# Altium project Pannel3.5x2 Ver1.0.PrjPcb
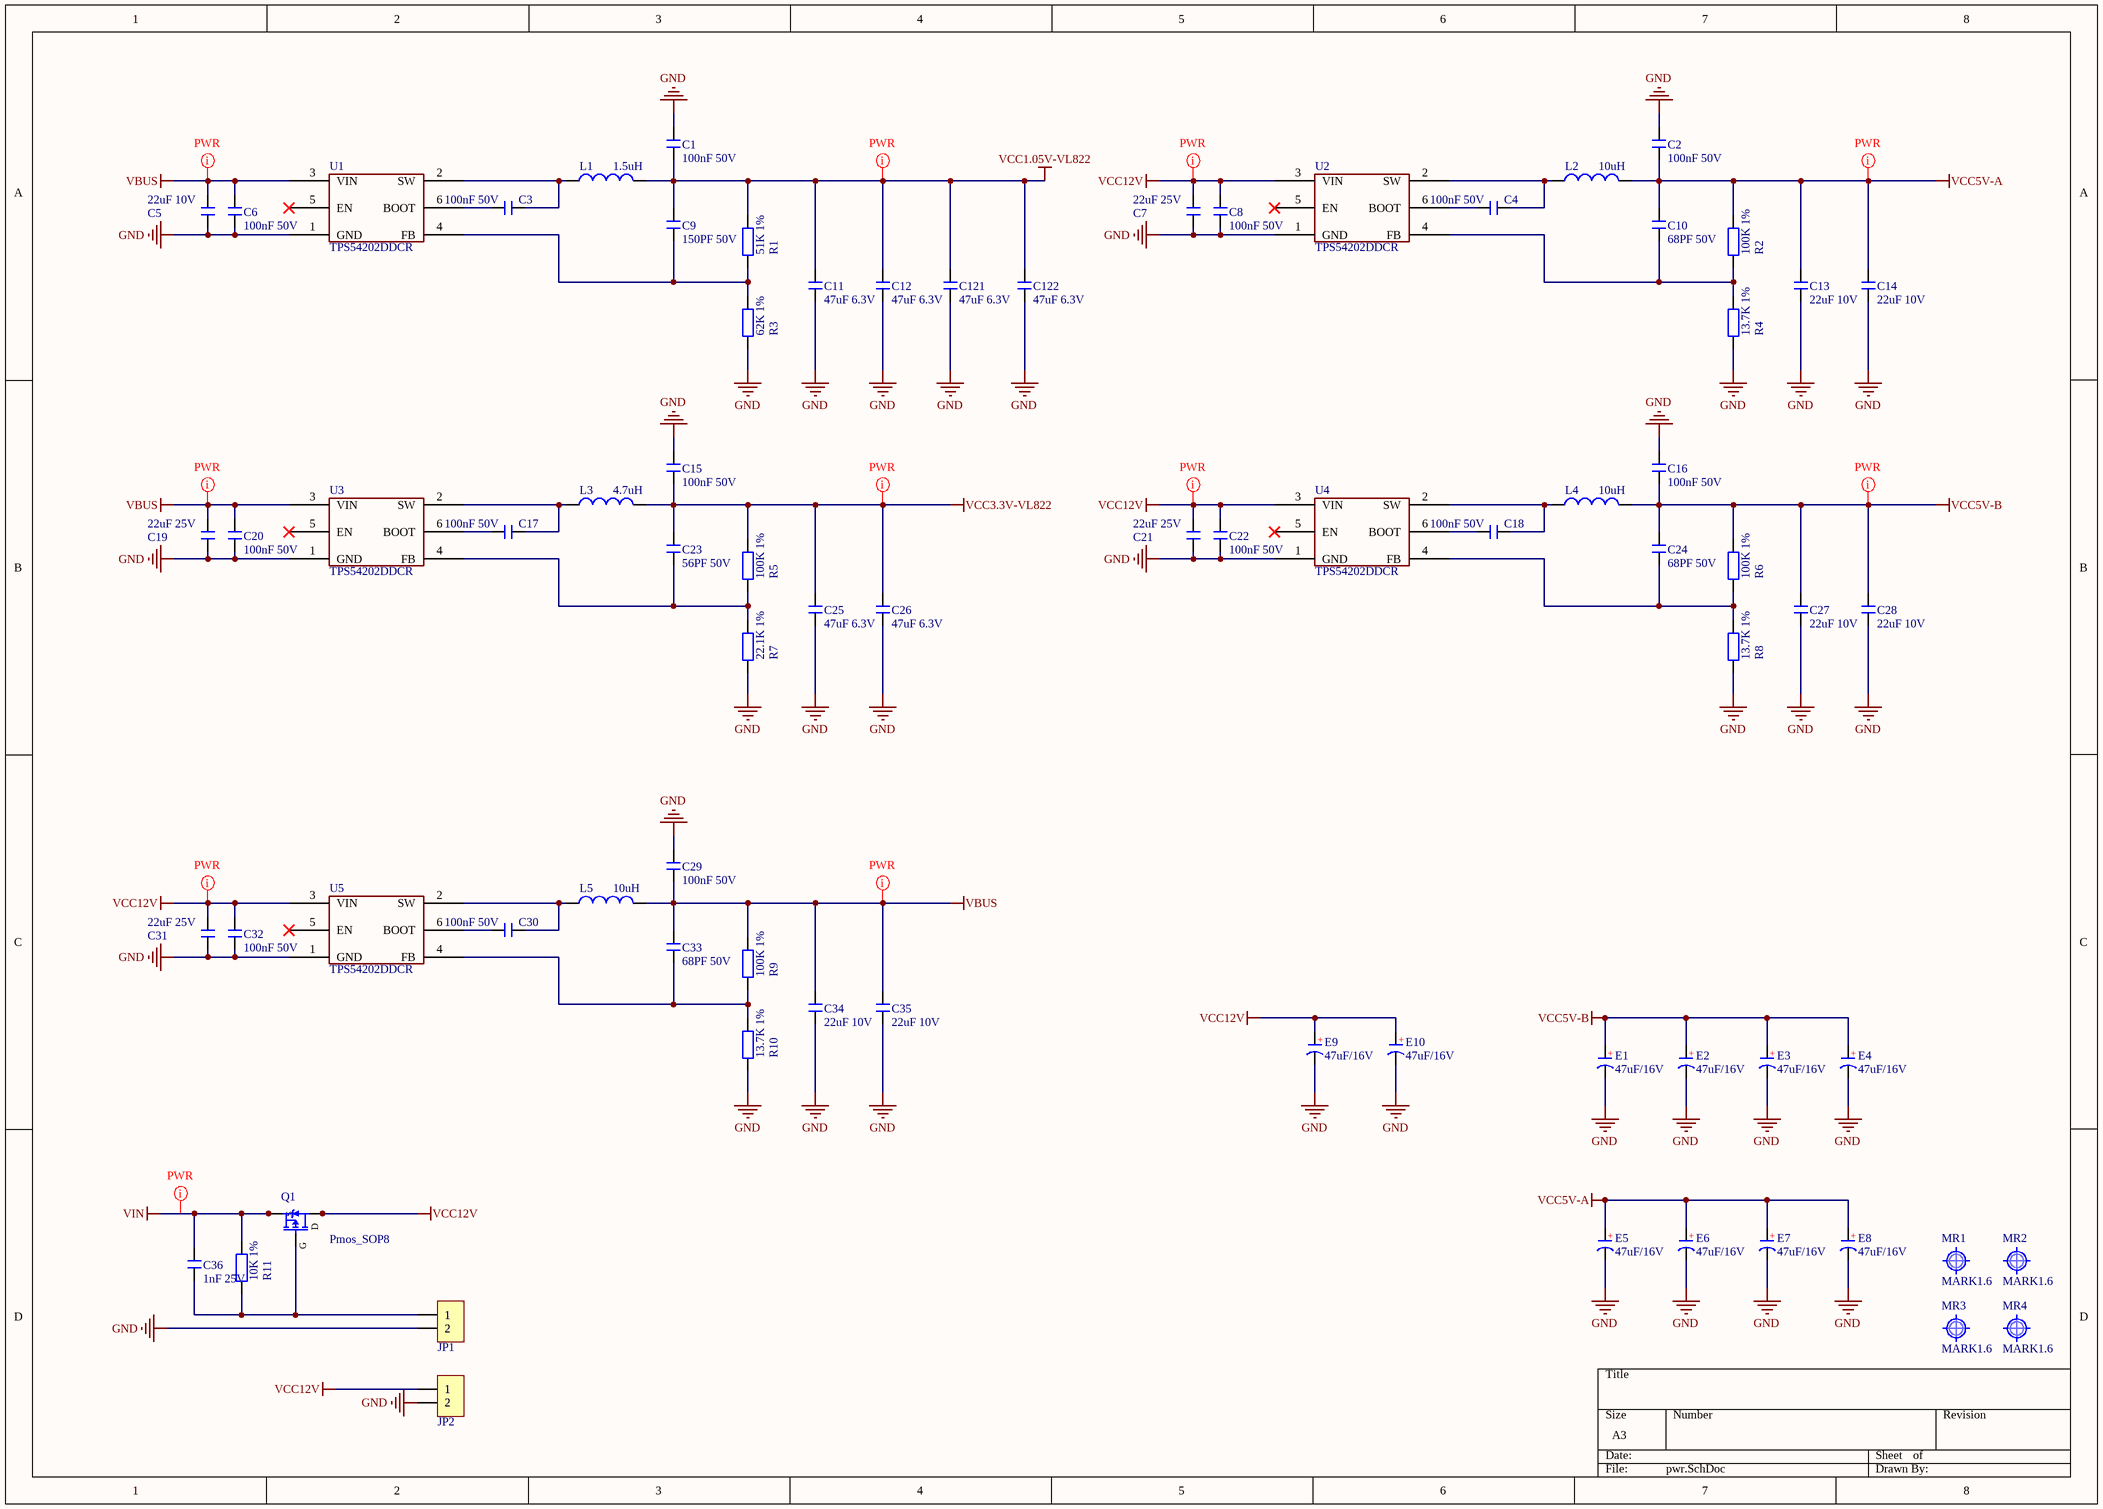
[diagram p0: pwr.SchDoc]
4 sheets, 222 parts. Net scope: global (net labels, ports and power ports of the same name join across sheets).
Board file: Pannel3.5x2 Ver0.2.PcbDoc
Sheets:
  pwr.SchDoc
  connector.SchDoc
  jmb575.SchDoc
  vl822.SchDoc

## Sheet pwr.SchDoc
size A3; SheetNumber: 1; SheetTotal: 4

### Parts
C1  100nF 50V  [C0402_L]
C2  100nF 50V  [C0402_L]
C3  100nF 50V  [C0402_L]
C4  100nF 50V  [C0402_L]
C5  22uF 10V  [C0805_L]
C6  100nF 50V  [C0402_L]
C7  22uF 25V  [C0805_L]
C8  100nF 50V  [C0402_L]
C9  150PF 50V  [C0402_L]
C10  68PF 50V  [C0402_L]
C11  47uF 6.3V  [C0805_L]
C12  47uF 6.3V  [C0805_L]
C13  22uF 10V  [C0805_L]
C14  22uF 10V  [C0805_L]
C15  100nF 50V  [C0402_L]
C16  100nF 50V  [C0402_L]
C17  100nF 50V  [C0402_L]
C18  100nF 50V  [C0402_L]
C19  22uF 25V  [C0805_L]
C20  100nF 50V  [C0402_L]
C21  22uF 25V  [C0805_L]
C22  100nF 50V  [C0402_L]
C23  56PF 50V  [C0402_L]
C24  68PF 50V  [C0402_L]
C25  47uF 6.3V  [C0805_L]
C26  47uF 6.3V  [C0805_L]
C27  22uF 10V  [C0805_L]
C28  22uF 10V  [C0805_L]
C29  100nF 50V  [C0402_L]
C30  100nF 50V  [C0402_L]
C31  22uF 25V  [C0805_L]
C32  100nF 50V  [C0402_L]
C33  68PF 50V  [C0402_L]
C34  22uF 10V  [C0805_L]
C35  22uF 10V  [C0805_L]
C36  1nF 25V  [C0402_L]
C121  47uF 6.3V  [C0805_L]
C122  47uF 6.3V  [C0805_L]
E1  47uF/16V  [CS 6*4 - R]
E2  47uF/16V  [CS 6*4 - R]
E3  47uF/16V  [CS 6*4 - R]
E4  47uF/16V  [CS 6*4 - R]
E5  47uF/16V  [CS 6*4 - R]
E6  47uF/16V  [CS 6*4 - R]
E7  47uF/16V  [CS 6*4 - R]
E8  47uF/16V  [CS 6*4 - R]
E9  47uF/16V  [CS 6*4 - R]
E10  47uF/16V  [CS 6*4 - R]
JP1  HDR-1X2  [ZH1.5-WS-2P]  (value not drawn)
JP2  HDR-1X2  [XH2.54-WS-2P]  (value not drawn)
L1  1.5uH  [SMMS0420]
L2  10uH  [SMMS0420]
L3  4.7uH  [SMMS0420]
L4  10uH  [SMMS0420]
L5  10uH  [SMMS0420]
MR1  MARK1.6  [Mark 1]
MR2  MARK1.6  [Mark 1]
MR3  MARK1.6  [Mark 1]
MR4  MARK1.6  [Mark 1]
Q1  Pmos_SOP8  [SOP8_L]
R1  51K 1%  [R0402_L]
R2  100K 1%  [R0402_L]
R3  62K 1%  [R0402_L]
R4  13.7K 1%  [R0402_L]
R5  100K 1%  [R0402_L]
R6  100K 1%  [R0402_L]
R7  22.1K 1%  [R0402_L]
R8  13.7K 1%  [R0402_L]
R9  100K 1%  [R0402_L]
R10  13.7K 1%  [R0402_L]
R11  10K 1%  [R0402_L]
U1  TPS54202DDCR  [SOT23-6L]
U2  TPS54202DDCR  [SOT23-6L]
U3  TPS54202DDCR  [SOT23-6L]
U4  TPS54202DDCR  [SOT23-6L]
U5  TPS54202DDCR  [SOT23-6L]

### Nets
GND: C1.2 C2.2 C5.1 C6.1 C7.1 C8.1 C11.2 C12.2 C13.2 C14.2 C15.2 C16.2 C19.1 C20.1 C21.1 C22.1 C25.2 C26.2 C27.2 C28.2 C29.2 C31.1 C32.1 C34.2 C35.2 C121.2 C122.2 E1.2(K) E2.2(K) E3.2(K) E4.2(K) E5.2(K) E6.2(K) E7.2(K) E8.2(K) E9.2(K) E10.2(K) JP1.2 JP2.2 R3.2 R4.2 R7.2 R8.2 R10.2 U1.1(GND) U2.1(GND) U3.1(GND) U4.1(GND) U5.1(GND)
VBUS: C5.2 C6.2 C19.2 C20.2 C29.1 C33.2 C34.1 C35.1 L5.2 R9.1 U1.3(VIN) U3.3(VIN)
VCC1.05V-VL822: C1.1 C9.2 C11.1 C12.1 C121.1 C122.1 L1.2 R1.1
VCC3.3V-VL822: C15.1 C23.2 C25.1 C26.1 L3.2 R5.1
VCC5V-A: C2.1 C10.2 C13.1 C14.1 E5.1(A) E6.1(A) E7.1(A) E8.1(A) L2.2 R2.1
VCC5V-B: C16.1 C24.2 C27.1 C28.1 E1.1(A) E2.1(A) E3.1(A) E4.1(A) L4.2 R6.1
VCC12V: C7.2 C8.2 C21.2 C22.2 C31.2 C32.2 E9.1(A) E10.1(A) JP2.1 Q1.5(D) Q1.6(D) Q1.7(D) Q1.8(D) U2.3(VIN) U4.3(VIN) U5.3(VIN)
VIN: C36.1 Q1.1(S) Q1.2(S) Q1.3(S) R11.1
NetC3_1: C3.1 U1.6(BOOT)
NetC3_2: C3.2 L1.1 U1.2(SW)
NetC4_1: C4.1 U2.6(BOOT)
NetC4_2: C4.2 L2.1 U2.2(SW)
NetC9_1: C9.1 R1.2 R3.1 U1.4(FB)
NetC10_1: C10.1 R2.2 R4.1 U2.4(FB)
NetC17_1: C17.1 U3.6(BOOT)
NetC17_2: C17.2 L3.1 U3.2(SW)
NetC18_1: C18.1 U4.6(BOOT)
NetC18_2: C18.2 L4.1 U4.2(SW)
NetC23_1: C23.1 R5.2 R7.1 U3.4(FB)
NetC24_1: C24.1 R6.2 R8.1 U4.4(FB)
NetC30_1: C30.1 U5.6(BOOT)
NetC30_2: C30.2 L5.1 U5.2(SW)
NetC33_1: C33.1 R9.2 R10.1 U5.4(FB)
NetC36_2: C36.2 JP1.1 Q1.4(G) R11.2

Not connected (* = marked no-connect by the designer): U1 5(EN)*; U2 5(EN)*; U3 5(EN)*; U4 5(EN)*; U5 5(EN)*

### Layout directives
net class PWR: VBUS, VCC1.05V-VL822, VCC3.3V-VL822, VCC5V-A, VCC5V-B, VCC12V, VIN

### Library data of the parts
C1-C36 C121 C122 = C: 无极性贴片电容; 版权归属: 源创客; 材质: X7R
E1-E10 = C-CD: 贴片电解电容; BOM名称: 贴片钽电容; 版权归属: 源创客
JP1 JP2 = Header 2: 2P接插件; 版权归属: 源创客
L1-L5 = L: 小功率贴片电感; 版权归属: 源创客
MR1-MR4 = MARK: 光学定位点; 版权归属: 源创客
Q1 = Pmos_SOP8: BOM名称: 场效应管; 版权归属: 源创客; 描述: P沟道 30V/4.2A
R1-R11 = R: 贴片电阻; 版权归属: 源创客
U1-U5 = TPS54202DDCR: DCDC Convert

## Sheet connector.SchDoc
size A4; SheetNumber: 2; SheetTotal: 4
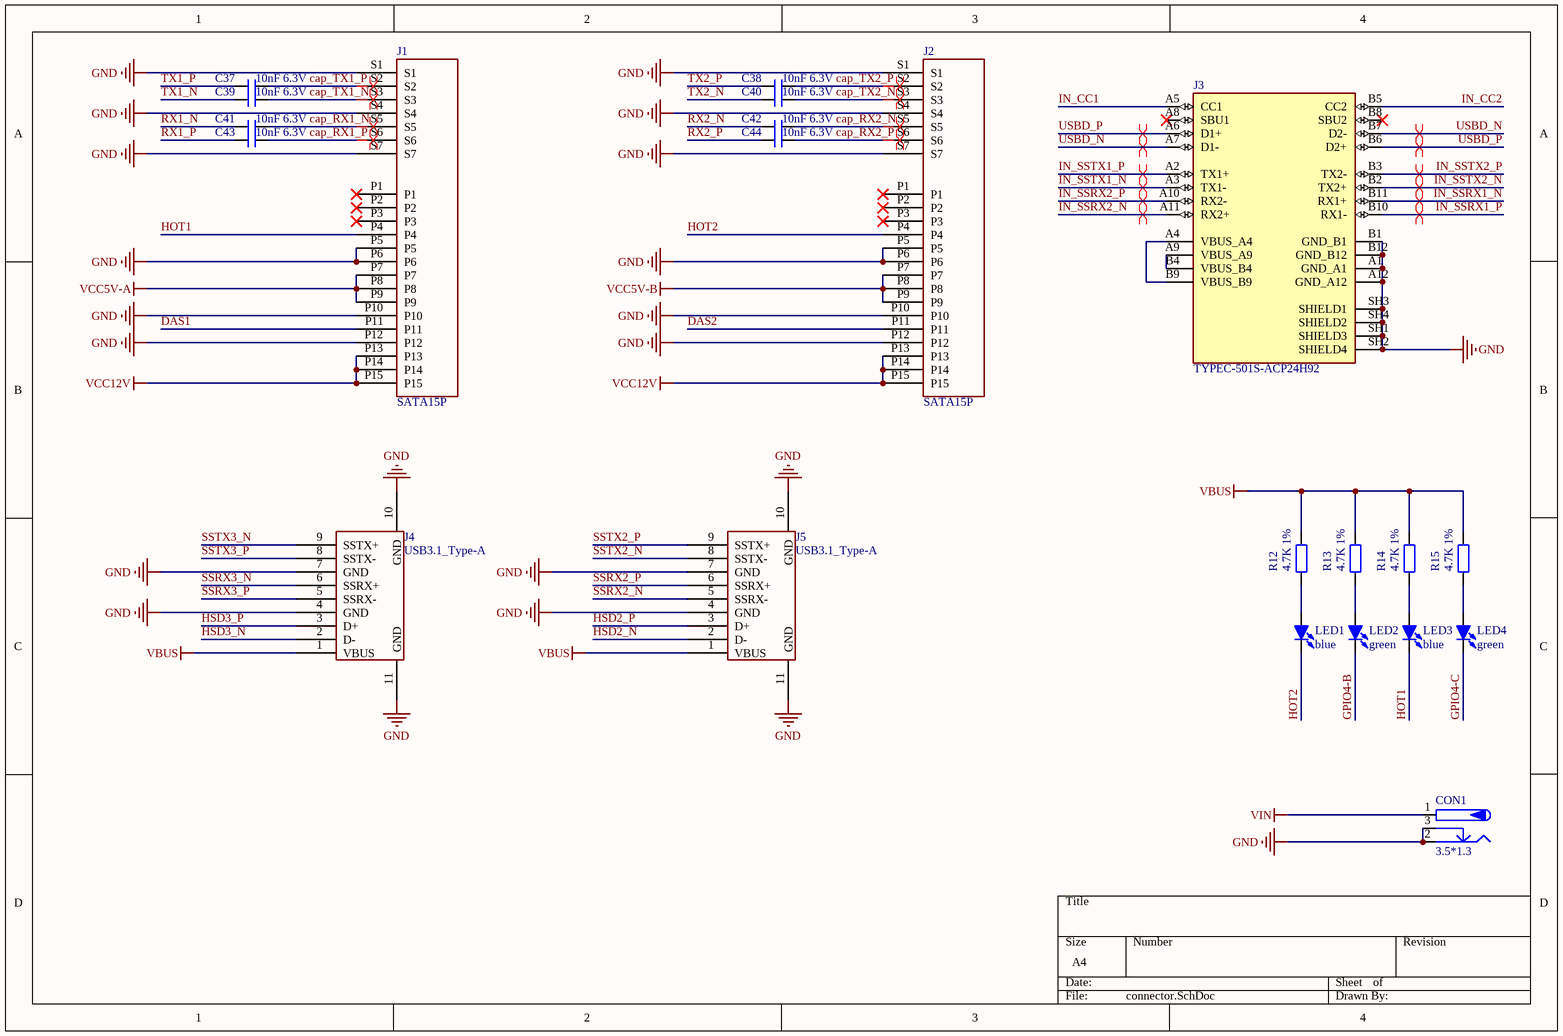
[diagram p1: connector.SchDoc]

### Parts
C37  10nF 6.3V  [C0402_L]
C38  10nF 6.3V  [C0402_L]
C39  10nF 6.3V  [C0402_L]
C40  10nF 6.3V  [C0402_L]
C41  10nF 6.3V  [C0402_L]
C42  10nF 6.3V  [C0402_L]
C43  10nF 6.3V  [C0402_L]
C44  10nF 6.3V  [C0402_L]
CON1  3.5*1.3  [DC-012G-2.5]
J1  SATA15P  [SATA 15P 贴片]
J2  SATA15P  [SATA 15P 贴片]
J3  TYPEC-501S-ACP24H92  [TypeC 24p 直立]
J4  USB3.1_Type-A  [USB3.1_Type-A 立式直插]
J5  USB3.1_Type-A  [USB3.1_Type-A 立式直插]
LED1  blue  [LED 0805B]
LED2  green  [LED 0805G]
LED3  blue  [LED 0805B]
LED4  green  [LED 0805G]
R12  4.7K 1%  [R0402_L]
R13  4.7K 1%  [R0402_L]
R14  4.7K 1%  [R0402_L]
R15  4.7K 1%  [R0402_L]

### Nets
GND: CON1.2 CON1.3 J1.P5 J1.P6 J1.P10 J1.P12 J1.S1 J1.S4 J1.S7 J2.P5 J2.P6 J2.P10 J2.P12 J2.S1 J2.S4 J2.S7 J3.A1(GND_A1) J3.A12(GND_A12) J3.B1(GND_B1) J3.B12(GND_B12) J3.SH1(SHIELD3) J3.SH2(SHIELD4) J3.SH3(SHIELD1) J3.SH4(SHIELD2) J4.4(GND) J4.7(GND) J4.10(GND) J4.11(GND) J5.4(GND) J5.7(GND) J5.10(GND) J5.11(GND)
VBUS: J4.1(VBUS) J5.1(VBUS) R12.1 R13.1 R14.1 R15.1
VCC5V-A: J1.P7 J1.P8 J1.P9
VCC5V-B: J2.P7 J2.P8 J2.P9
VCC12V: J1.P13 J1.P14 J1.P15 J2.P13 J2.P14 J2.P15
VIN: CON1.1
cap_RX1_N: C41.1 J1.S5
cap_RX1_P: C43.1 J1.S6
cap_RX2_N: C42.1 J2.S5
cap_RX2_P: C44.1 J2.S6
cap_TX1_N: C39.1 J1.S3
cap_TX1_P: C37.1 J1.S2
cap_TX2_N: C40.1 J2.S3
cap_TX2_P: C38.1 J2.S2
DAS1: J1.P11
DAS2: J2.P11
GPIO4-B: LED2.2(K)
GPIO4-C: LED4.2(K)
HOT1: J1.P4 LED3.2(K)
HOT2: J2.P4 LED1.2(K)
HSD2_N: J5.2(D-)
HSD2_P: J5.3(D+)
HSD3_N: J4.2(D-)
HSD3_P: J4.3(D+)
IN_CC1: J3.A5(CC1)
IN_CC2: J3.B5(CC2)
IN_SSRX1_N: J3.B11(RX1+)
IN_SSRX1_P: J3.B10(RX1-)
IN_SSRX2_N: J3.A11(RX2+)
IN_SSRX2_P: J3.A10(RX2-)
IN_SSTX1_N: J3.A3(TX1-)
IN_SSTX1_P: J3.A2(TX1+)
IN_SSTX2_N: J3.B2(TX2+)
IN_SSTX2_P: J3.B3(TX2-)
RX1_N: C41.2
RX1_P: C43.2
RX2_N: C42.2
RX2_P: C44.2
SSRX2_N: J5.5(SSRX-)
SSRX2_P: J5.6(SSRX+)
SSRX3_N: J4.6(SSRX+)
SSRX3_P: J4.5(SSRX-)
SSTX2_N: J5.8(SSTX-)
SSTX2_P: J5.9(SSTX+)
SSTX3_N: J4.9(SSTX+)
SSTX3_P: J4.8(SSTX-)
TX1_N: C39.2
TX1_P: C37.2
TX2_N: C40.2
TX2_P: C38.2
USBD_N: J3.A7(D1-) J3.B7(D2-)
USBD_P: J3.A6(D1+) J3.B6(D2+)
NetJ3_A4: J3.A4(VBUS_A4) J3.B9(VBUS_B9)
NetJ3_A9: J3.A9(VBUS_A9) J3.B4(VBUS_B4)
NetLED1_1: LED1.1(A) R12.2
NetLED2_1: LED2.1(A) R13.2
NetLED3_1: LED3.1(A) R14.2
NetLED4_1: LED4.1(A) R15.2

Not connected (* = marked no-connect by the designer): J1 P1* P2* P3*; J2 P1* P2* P3*; J3 A8(SBU1)* B8(SBU2)*

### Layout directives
differential pair: cap_RX1_N, cap_RX1_P, cap_RX2_N, cap_RX2_P, cap_TX1_N, cap_TX1_P, cap_TX2_N, cap_TX2_P, IN_SSRX1_N, IN_SSRX1_P, IN_SSRX2_N, IN_SSRX2_P, IN_SSTX1_N, IN_SSTX1_P, IN_SSTX2_N, IN_SSTX2_P, USBD_N, USBD_P

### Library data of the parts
C37-C44 = C: 无极性贴片电容; 版权归属: 源创客; 材质: X7R
CON1 = P-DC: 低压电源接口; BOM名称: DC电源接口; 版权归属: 源创客
J3 = Typec 24p: USB-C (USB TYPE-C) USB 3.2 Gen 2 (USB 3.1 Gen 2, Superspeed + (USB 3.1)) Receptacle Connector 24 Position Surface Mount, Right Angle; Through Hole; MF: Molex; MP: 1054500101
J4 J5 = USB3.1_Type-A: USB接口
LED1-LED4 = LED-3MM: 插件LED; 版权归属: 源创客
R12-R15 = R: 贴片电阻; 版权归属: 源创客

## Sheet jmb575.SchDoc
size A2; SheetNumber: 3; SheetTotal: 4
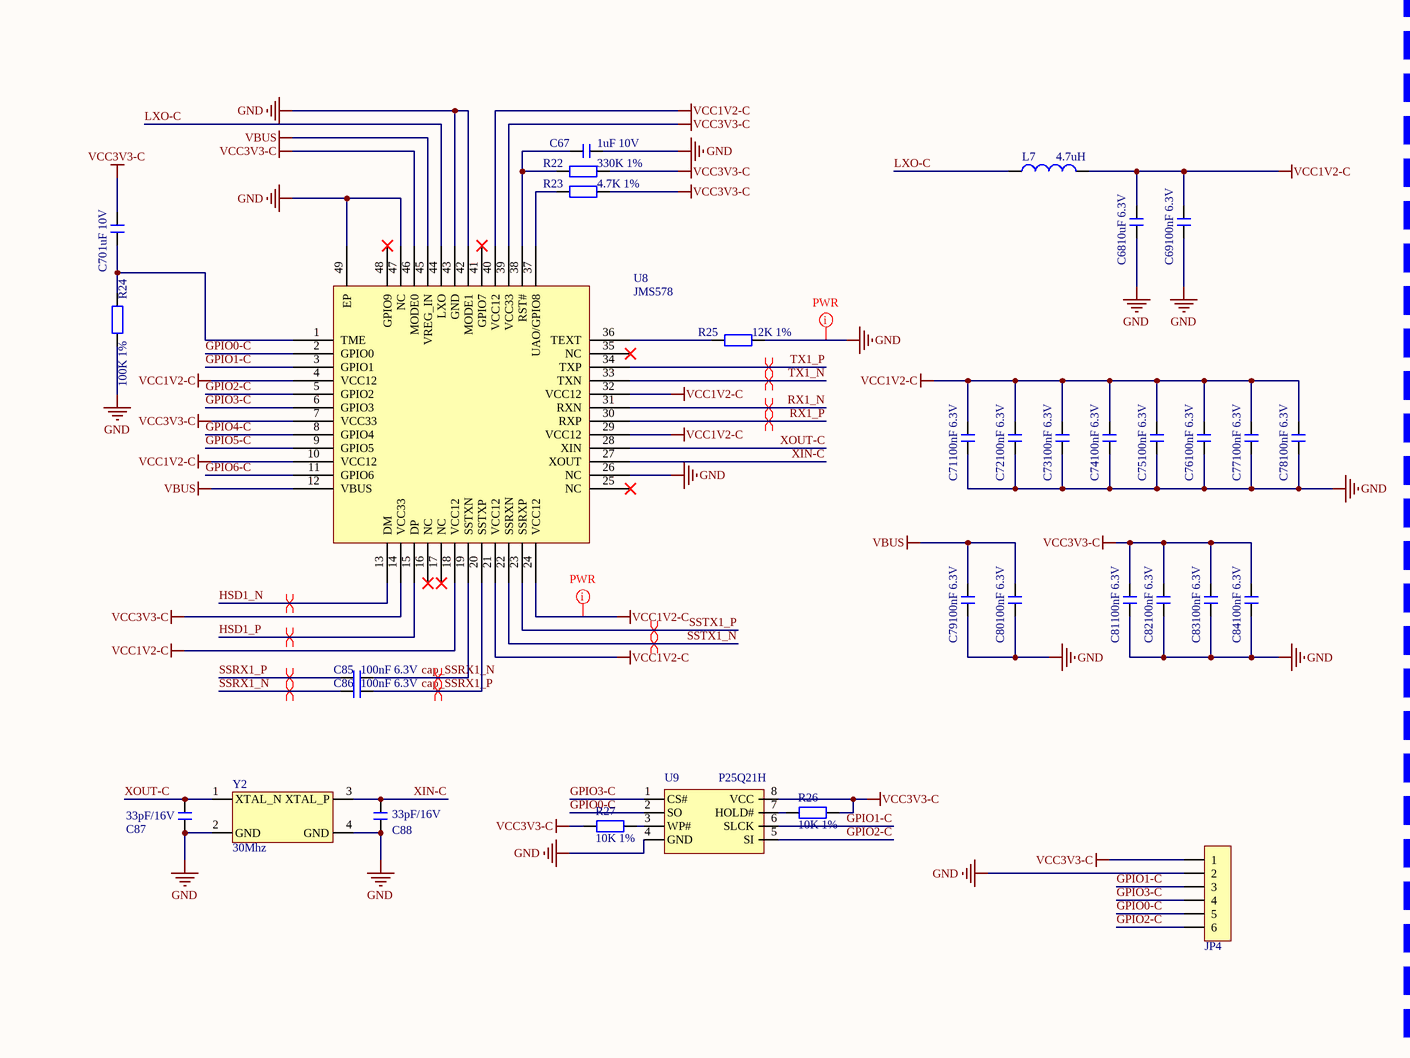
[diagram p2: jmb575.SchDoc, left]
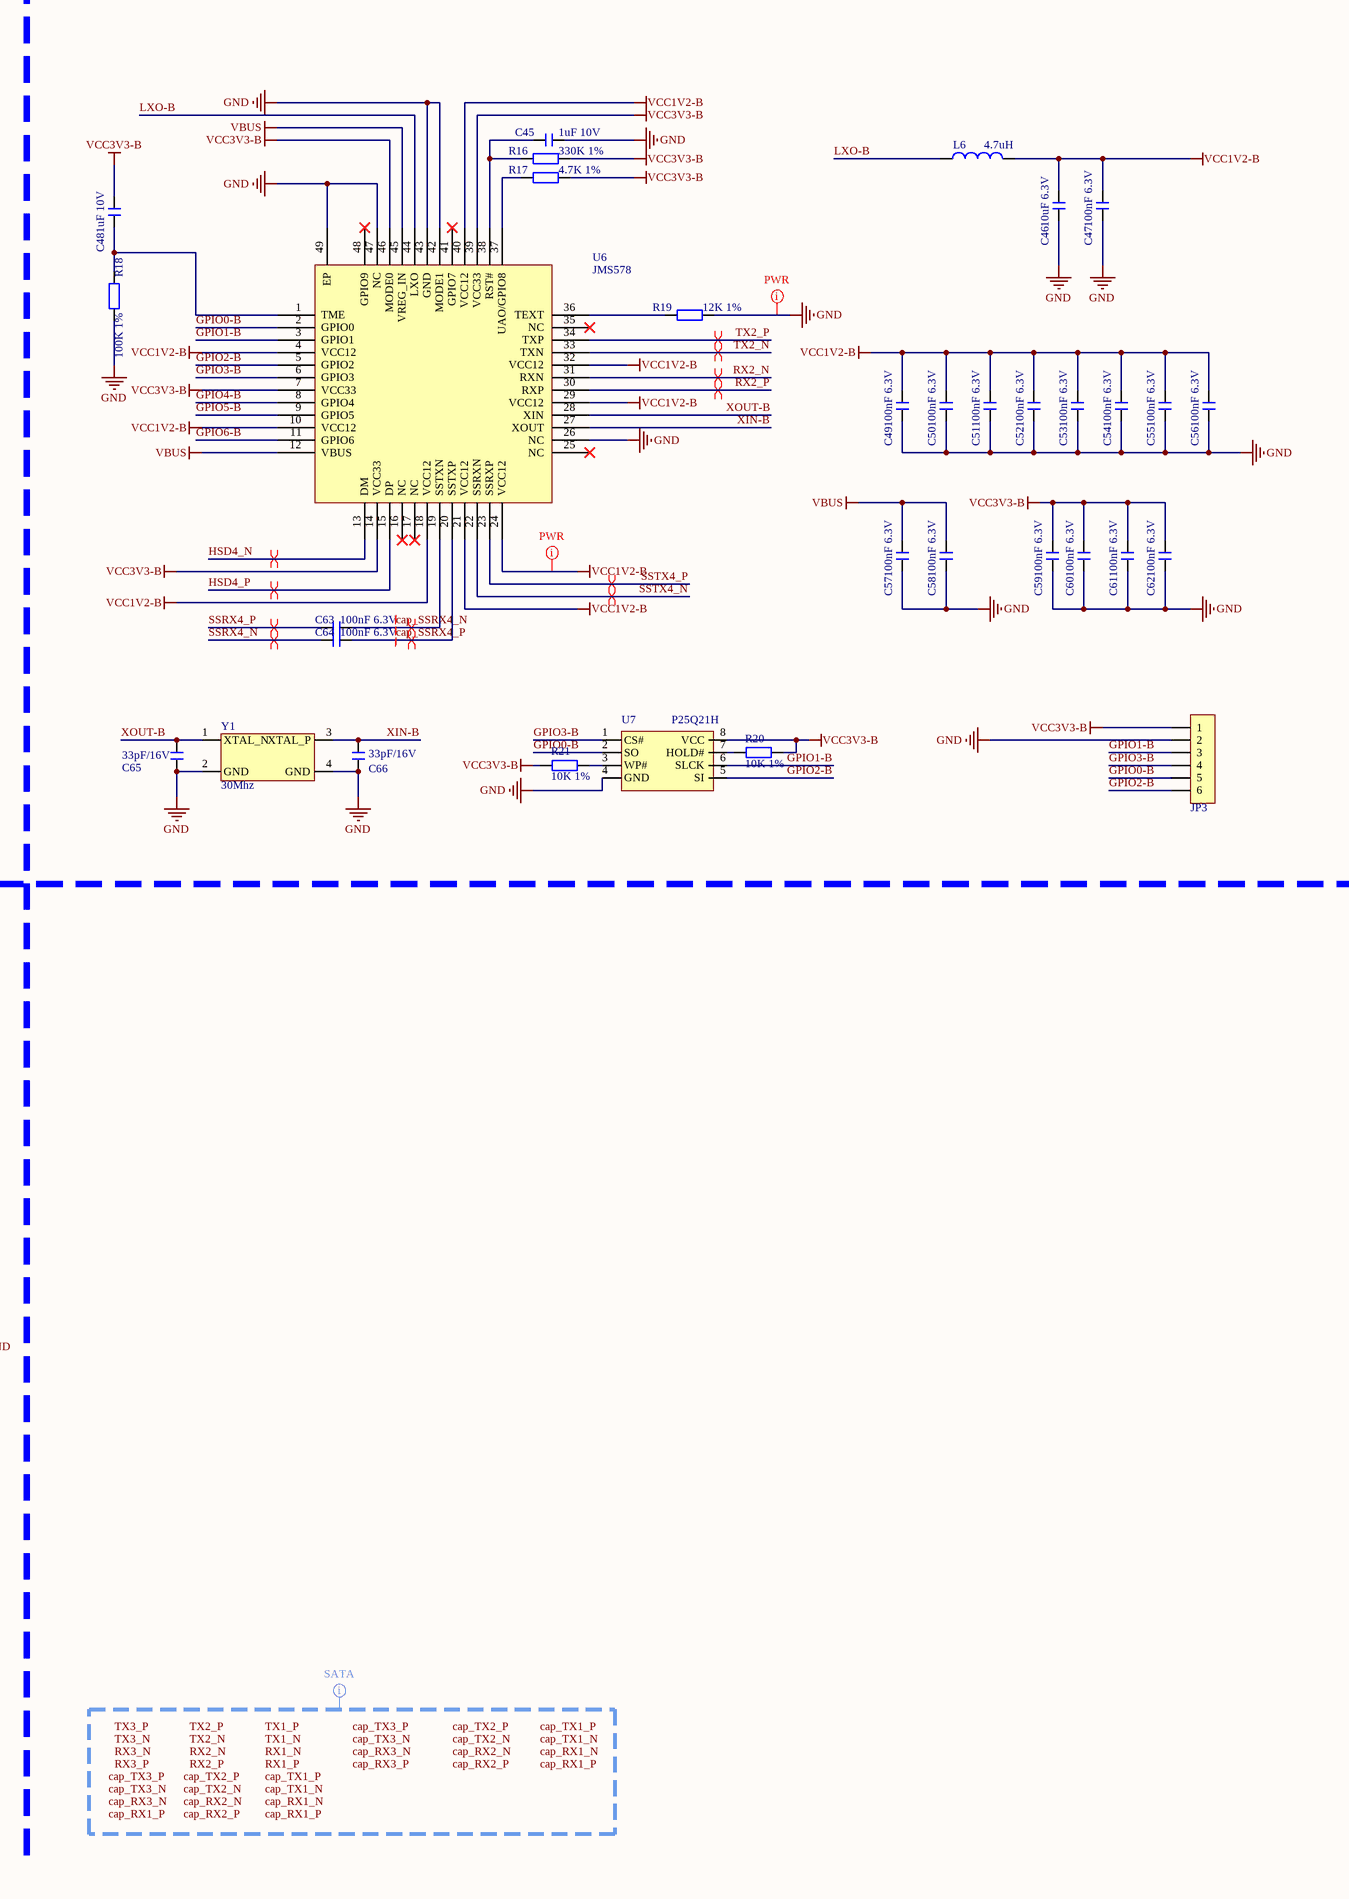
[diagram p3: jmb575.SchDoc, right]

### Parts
C45  1uF 10V  [C0402_L]
C46  10uF 6.3V  [C0603_L]
C47  100nF 6.3V  [C0402_L]
C48  1uF 10V  [C0402_L]
C49  100nF 6.3V  [C0402_L]
C50  100nF 6.3V  [C0402_L]
C51  100nF 6.3V  [C0402_L]
C52  100nF 6.3V  [C0402_L]
C53  100nF 6.3V  [C0402_L]
C54  100nF 6.3V  [C0402_L]
C55  100nF 6.3V  [C0402_L]
C56  100nF 6.3V  [C0402_L]
C57  100nF 6.3V  [C0402_L]
C58  100nF 6.3V  [C0402_L]
C59  100nF 6.3V  [C0402_L]
C60  100nF 6.3V  [C0402_L]
C61  100nF 6.3V  [C0402_L]
C62  100nF 6.3V  [C0402_L]
C63  100nF 6.3V  [C0402_L]
C64  100nF 6.3V  [C0402_L]
C65  33pF/16V  [C0402_L]
C66  33pF/16V  [C0402_L]
C67  1uF 10V  [C0402_L]
C68  10uF 6.3V  [C0603_L]
C69  100nF 6.3V  [C0402_L]
C70  1uF 10V  [C0402_L]
C71  100nF 6.3V  [C0402_L]
C72  100nF 6.3V  [C0402_L]
C73  100nF 6.3V  [C0402_L]
C74  100nF 6.3V  [C0402_L]
C75  100nF 6.3V  [C0402_L]
C76  100nF 6.3V  [C0402_L]
C77  100nF 6.3V  [C0402_L]
C78  100nF 6.3V  [C0402_L]
C79  100nF 6.3V  [C0402_L]
C80  100nF 6.3V  [C0402_L]
C81  100nF 6.3V  [C0402_L]
C82  100nF 6.3V  [C0402_L]
C83  100nF 6.3V  [C0402_L]
C84  100nF 6.3V  [C0402_L]
C85  100nF 6.3V  [C0402_L]
C86  100nF 6.3V  [C0402_L]
C87  33pF/16V  [C0402_L]
C88  33pF/16V  [C0402_L]
JP3  HDR-1X6  [6p烧录点]  (value not drawn)
JP4  HDR-1X6  [6p烧录点]  (value not drawn)
L6  4.7uH  [SMMS0420]
L7  4.7uH  [SMMS0420]
R16  330K 1%  [R0402_L]
R17  4.7K 1%  [R0402_L]
R18  100K 1%  [R0402_L]
R19  12K 1%  [R0402_L]
R20  10K 1%  [R0402_L]
R21  10K 1%  [R0402_L]
R22  330K 1%  [R0402_L]
R23  4.7K 1%  [R0402_L]
R24  100K 1%  [R0402_L]
R25  12K 1%  [R0402_L]
R26  10K 1%  [R0402_L]
R27  10K 1%  [R0402_L]
U6  JMS578  [QFN48-L6.0-W6.0-P0.4]
U7  P25Q21H  [SOP8_L]
U8  JMS578  [QFN48-L6.0-W6.0-P0.4]
U9  P25Q21H  [SOP8_L]
Y1  30Mhz  [OSC 3225-4P]
Y2  30Mhz  [OSC 3225-4P]

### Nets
GND: C45.1 C46.1 C47.1 C49.1 C50.1 C51.1 C52.1 C53.1 C54.1 C55.1 C56.1 C57.1 C58.1 C59.1 C60.1 C61.1 C62.1 C65.2 C66.2 C67.1 C68.1 C69.1 C71.1 C72.1 C73.1 C74.1 C75.1 C76.1 C77.1 C78.1 C79.1 C80.1 C81.1 C82.1 C83.1 C84.1 C87.2 C88.2 JP3.2 JP4.2 R18.1 R19.1 R24.1 R25.1 U6.26(NC) U6.42(MODE1) U6.43(GND) U6.47(NC) U6.49(EP) U7.4(GND) U8.26(NC) U8.42(MODE1) U8.43(GND) U8.47(NC) U8.49(EP) U9.4(GND) Y1.2(GND) Y1.4(GND) Y2.2(GND) Y2.4(GND)
VBUS: C57.2 C58.2 C79.2 C80.2 U6.12(VBUS) U6.45(VREG_IN) U8.12(VBUS) U8.45(VREG_IN)
VCC1V2-B: C46.2 C47.2 C49.2 C50.2 C51.2 C52.2 C53.2 C54.2 C55.2 C56.2 L6.2 U6.4(VCC12) U6.10(VCC12) U6.18(VCC12) U6.21(VCC12) U6.24(VCC12) U6.29(VCC12) U6.32(VCC12) U6.40(VCC12)
VCC1V2-C: C68.2 C69.2 C71.2 C72.2 C73.2 C74.2 C75.2 C76.2 C77.2 C78.2 L7.2 U8.4(VCC12) U8.10(VCC12) U8.18(VCC12) U8.21(VCC12) U8.24(VCC12) U8.29(VCC12) U8.32(VCC12) U8.40(VCC12)
VCC3V3-B: C48.2 C59.2 C60.2 C61.2 C62.2 JP3.1 R16.1 R17.1 R20.1 R21.1 U6.7(VCC33) U6.14(VCC33) U6.39(VCC33) U6.46(MODE0) U7.8(VCC)
VCC3V3-C: C70.2 C81.2 C82.2 C83.2 C84.2 JP4.1 R22.1 R23.1 R26.1 R27.2 U8.7(VCC33) U8.14(VCC33) U8.39(VCC33) U8.46(MODE0) U9.8(VCC)
cap_SSRX1_N: C85.2 U8.19(SSTXN)
cap_SSRX1_P: C86.2 U8.20(SSTXP)
cap_SSRX4_N: C63.2 U6.19(SSTXN)
cap_SSRX4_P: C64.2 U6.20(SSTXP)
GPIO0-B: JP3.5 U6.2(GPIO0) U7.2(SO)
GPIO0-C: JP4.5 U8.2(GPIO0) U9.2(SO)
GPIO1-B: JP3.3 U6.3(GPIO1) U7.6(SLCK)
GPIO1-C: JP4.3 U8.3(GPIO1) U9.6(SLCK)
GPIO2-B: JP3.6 U6.5(GPIO2) U7.5(SI)
GPIO2-C: JP4.6 U8.5(GPIO2) U9.5(SI)
GPIO3-B: JP3.4 U6.6(GPIO3) U7.1(CS#)
GPIO3-C: JP4.4 U8.6(GPIO3) U9.1(CS#)
GPIO4-B: U6.8(GPIO4)
GPIO4-C: U8.8(GPIO4)
GPIO5-B: U6.9(GPIO5)
GPIO5-C: U8.9(GPIO5)
GPIO6-B: U6.11(GPIO6)
GPIO6-C: U8.11(GPIO6)
HSD1_N: U8.13(DM)
HSD1_P: U8.15(DP)
HSD4_N: U6.13(DM)
HSD4_P: U6.15(DP)
LXO-B: L6.1 U6.44(LXO)
LXO-C: L7.1 U8.44(LXO)
RX1_N: U8.31(RXN)
RX1_P: U8.30(RXP)
RX2_N: U6.31(RXN)
RX2_P: U6.30(RXP)
SSRX1_N: C86.1
SSRX1_P: C85.1
SSRX4_N: C64.1
SSRX4_P: C63.1
SSTX1_N: U8.22(SSRXN)
SSTX1_P: U8.23(SSRXP)
SSTX4_N: U6.22(SSRXN)
SSTX4_P: U6.23(SSRXP)
TX1_N: U8.33(TXN)
TX1_P: U8.34(TXP)
TX2_N: U6.33(TXN)
TX2_P: U6.34(TXP)
XIN-B: C66.1 U6.27(XOUT) Y1.3(XTAL_P)
XIN-C: C88.1 U8.27(XOUT) Y2.3(XTAL_P)
XOUT-B: C65.1 U6.28(XIN) Y1.1(XTAL_N)
XOUT-C: C87.1 U8.28(XIN) Y2.1(XTAL_N)
NetC45_2: C45.2 R16.2 U6.38(RST#)
NetC48_1: C48.1 R18.2 U6.1(TME)
NetC67_2: C67.2 R22.2 U8.38(RST#)
NetC70_1: C70.1 R24.2 U8.1(TME)
NetR17_2: R17.2 U6.37(UAO/GPIO8)
NetR19_2: R19.2 U6.36(TEXT)
NetR20_2: R20.2 U7.7(HOLD#)
NetR21_2: R21.2 U7.3(WP#)
NetR23_2: R23.2 U8.37(UAO/GPIO8)
NetR25_2: R25.2 U8.36(TEXT)
NetR26_2: R26.2 U9.7(HOLD#)
NetR27_1: R27.1 U9.3(WP#)

Not connected (* = marked no-connect by the designer): U6 16(NC)* 17(NC)* 25(NC)* 35(NC)* 41(GPIO7)* 48(GPIO9)*; U8 16(NC)* 17(NC)* 25(NC)* 35(NC)* 41(GPIO7)* 48(GPIO9)*

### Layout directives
differential pair: cap_SSRX1_N, cap_SSRX1_P, cap_SSRX4_N, cap_SSRX4_P, HSD1_N, HSD1_P, HSD4_N, HSD4_P, RX1_N, RX1_P, RX2_N, RX2_P, SSRX1_N, SSRX1_P, SSRX4_N, SSRX4_P, SSTX1_N, SSTX1_P, SSTX4_N, SSTX4_P, TX1_N, TX1_P, TX2_N, TX2_P
net class PWR: GND, VCC1V2-B, VCC1V2-C
net class SATA; rule Differential Pairs Routing [Pref Gap = 6mil    Min Gap  = 6mil    Max Gap  = 6milPref Width = 4.29mil    Min Width  = 4.29mil    Max Width  = 4.29mil]; rule Routing Via Style [Pref Size = 0.4mm    Pref Hole Size = 0.3mm]: cap_RX1_N, cap_RX1_P, cap_RX2_N, cap_RX2_P, cap_RX3_N, cap_RX3_P, cap_TX1_N, cap_TX1_P, cap_TX2_N, cap_TX2_P, cap_TX3_N, cap_TX3_P, RX1_N, RX1_P, RX2_N, RX2_P, RX3_N, RX3_P, TX1_N, TX1_P, TX2_N, TX2_P, TX3_N, TX3_P

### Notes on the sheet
- Labels drawn without touching a wire or pin: cap_RX1_N, cap_RX1_P, cap_RX2_N, cap_RX2_P, cap_RX3_N, cap_RX3_P, cap_TX1_N, cap_TX1_P, cap_TX2_N, cap_TX2_P, cap_TX3_N, cap_TX3_P, RX1_N, RX1_P, RX2_N, RX2_P, RX3_N, RX3_P, TX1_N, TX1_P, TX2_N, TX2_P, TX3_N, TX3_P

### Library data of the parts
C45-C88 = C: 无极性贴片电容; 版权归属: 源创客; 材质: X7R
JP3 JP4 = Header 6: 6P接插件; 版权归属: 源创客
L6 L7 = L: 小功率贴片电感; 版权归属: 源创客
R16-R27 = R: 贴片电阻; 版权归属: 源创客
U7 U9 = P25D40H
Y1 Y2 = Crystal

## Sheet vl822.SchDoc
size A3; SheetNumber: 4; SheetTotal: 4
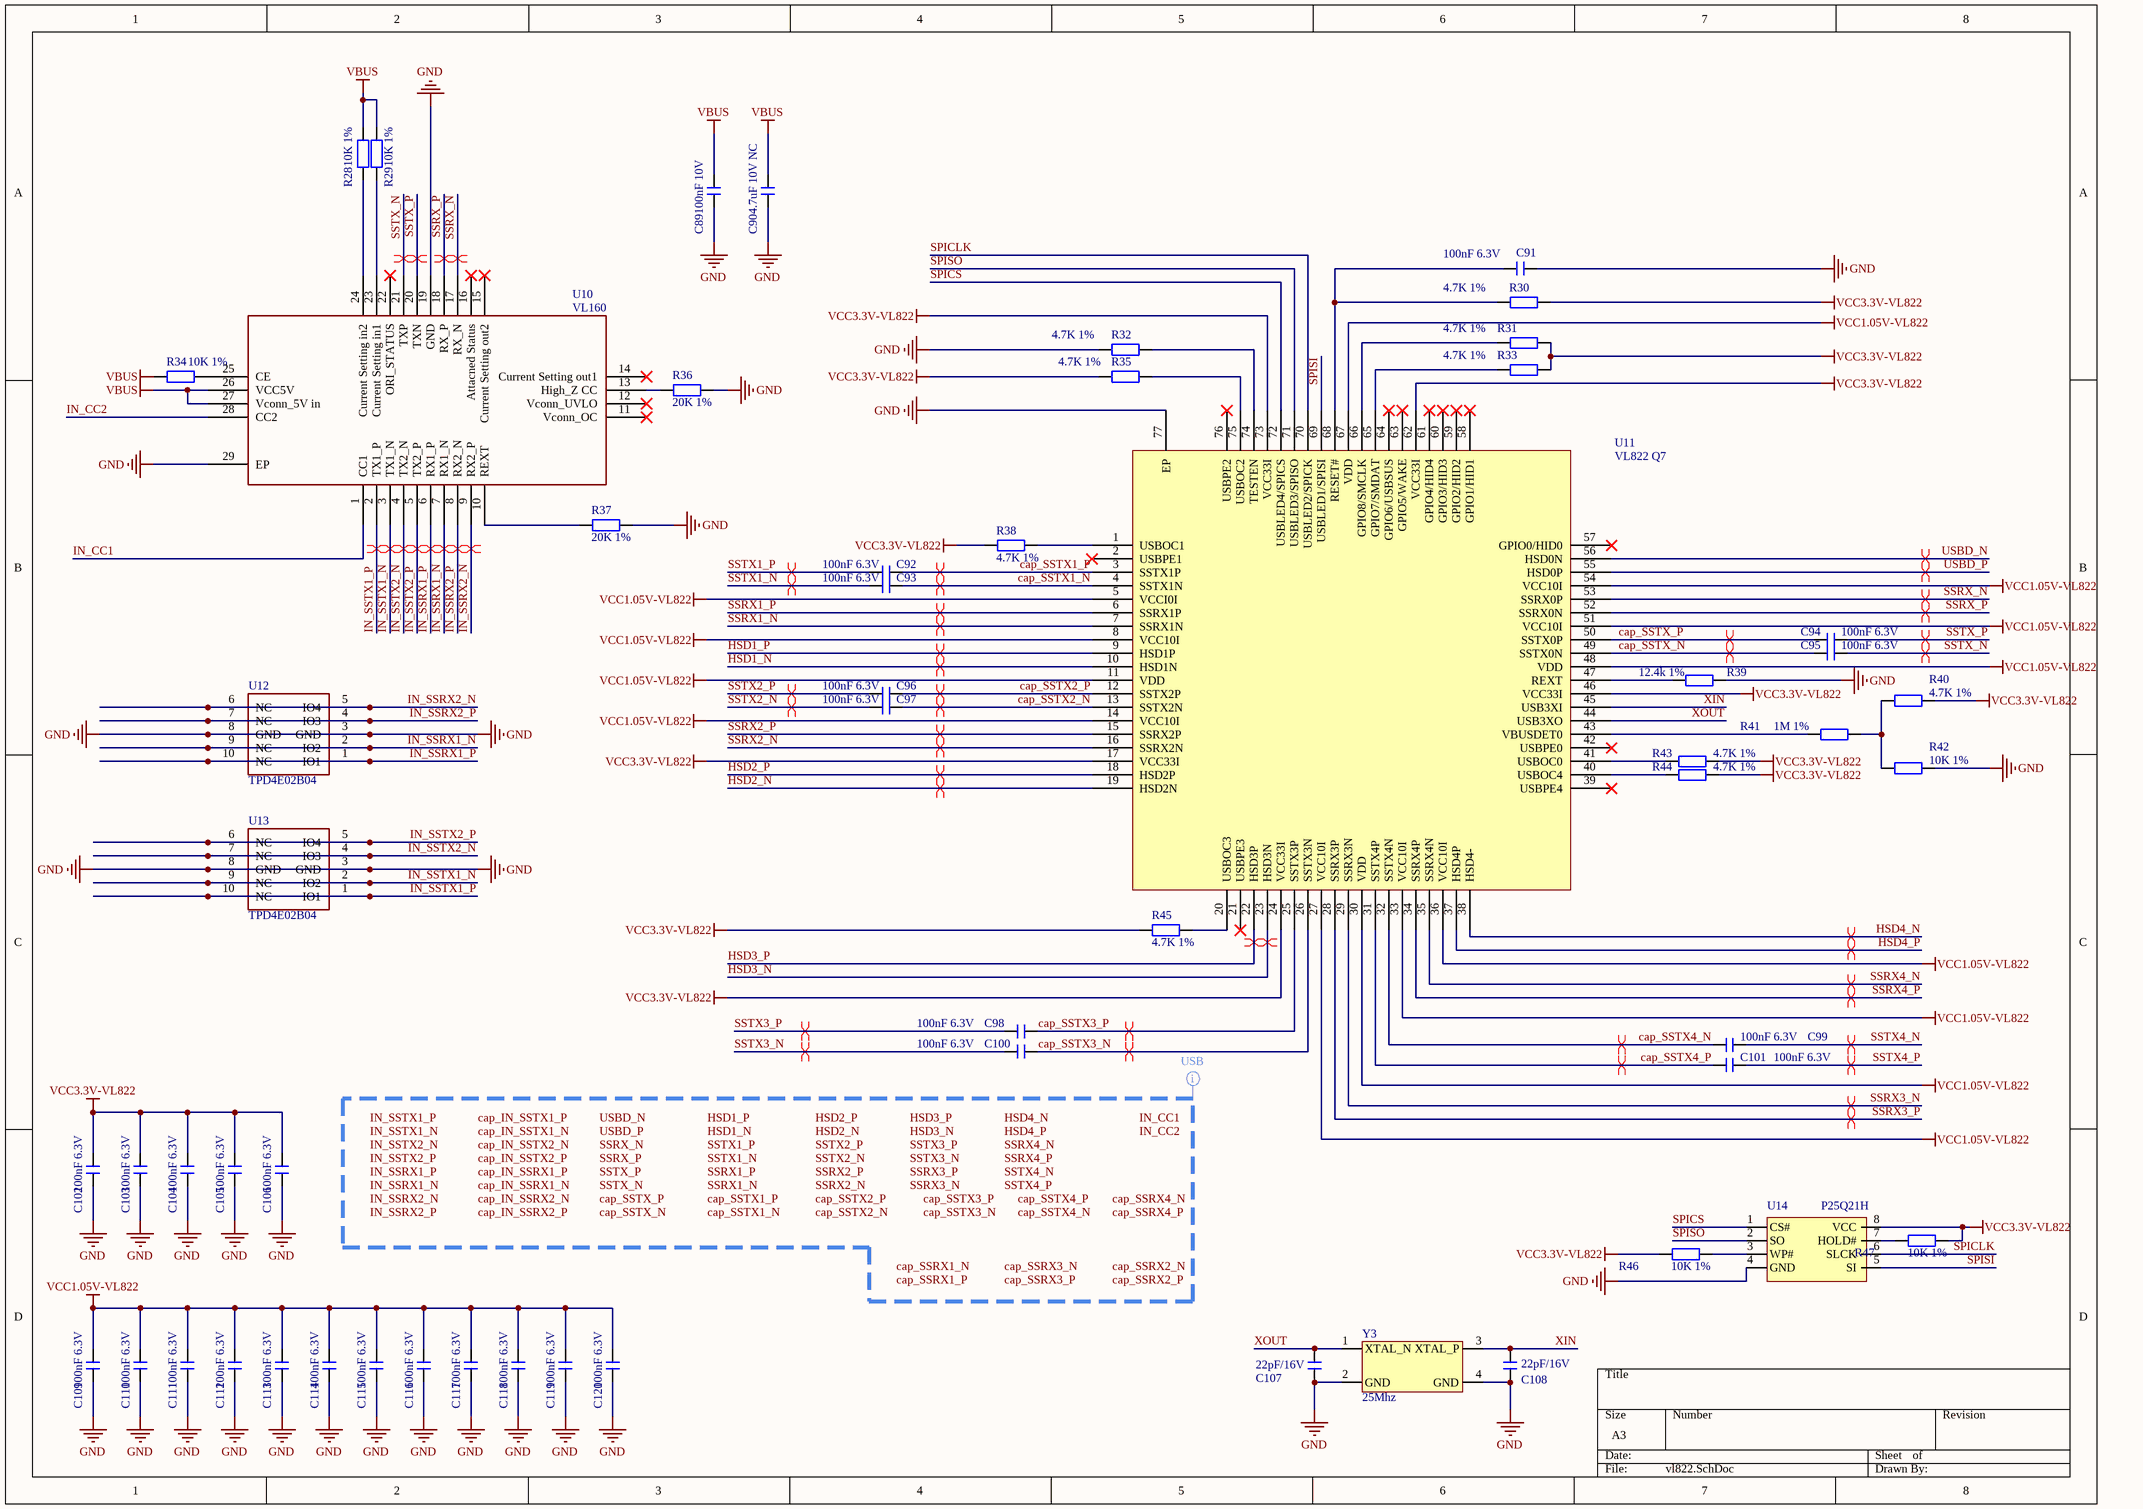
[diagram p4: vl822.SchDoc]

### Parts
C89  100nF 10V  [C0402_L]
C90  4.7uF 10V NC  [C0402_L]
C91  100nF 6.3V  [C0402_L]
C92  100nF 6.3V  [C0402_L]
C93  100nF 6.3V  [C0402_L]
C94  100nF 6.3V  [C0402_L]
C95  100nF 6.3V  [C0402_L]
C96  100nF 6.3V  [C0402_L]
C97  100nF 6.3V  [C0402_L]
C98  100nF 6.3V  [C0402_L]
C99  100nF 6.3V  [C0402_L]
C100  100nF 6.3V  [C0402_L]
C101  100nF 6.3V  [C0402_L]
C102  100nF 6.3V  [C0402_L]
C103  100nF 6.3V  [C0402_L]
C104  100nF 6.3V  [C0402_L]
C105  100nF 6.3V  [C0402_L]
C106  100nF 6.3V  [C0402_L]
C107  22pF/16V  [C0402_L]
C108  22pF/16V  [C0402_L]
C109  100nF 6.3V  [C0402_L]
C110  100nF 6.3V  [C0402_L]
C111  100nF 6.3V  [C0402_L]
C112  100nF 6.3V  [C0402_L]
C113  100nF 6.3V  [C0402_L]
C114  100nF 6.3V  [C0402_L]
C115  100nF 6.3V  [C0402_L]
C116  100nF 6.3V  [C0402_L]
C117  100nF 6.3V  [C0402_L]
C118  100nF 6.3V  [C0402_L]
C119  100nF 6.3V  [C0402_L]
C120  100nF 6.3V  [C0402_L]
R28  10K 1%  [R0402_L]
R29  10K 1%  [R0402_L]
R30  4.7K 1%  [R0402_L]
R31  4.7K 1%  [R0402_L]
R32  4.7K 1%  [R0402_L]
R33  4.7K 1%  [R0402_L]
R34  10K 1%  [R0402_L]
R35  4.7K 1%  [R0402_L]
R36  20K 1%  [R0402_L]
R37  20K 1%  [R0402_L]
R38  4.7K 1%  [R0402_L]
R39  12.4k 1%  [R0402_L]
R40  4.7K 1%  [R0402_L]
R41  1M 1%  [R0402_L]
R42  10K 1%  [R0402_L]
R43  4.7K 1%  [R0402_L]
R44  4.7K 1%  [R0402_L]
R45  4.7K 1%  [R0402_L]
R46  10K 1%  [R0402_L]
R47  10K 1%  [R0402_L]
U10  VL160  [MQFN-28_L4.5-W3.5-P0.40-BL-EP]
U11  VL822 Q7  [QFN-76_L9.0-W9.0-P0.40-EP6.3-TL]
U12  TPD4E02B04  [DIO_TPD4E02B04DQAR]
U13  TPD4E02B04  [DIO_TPD4E02B04DQAR]
U14  P25Q21H  [SOP8_L]
Y3  25Mhz  [OSC 3225-4P]

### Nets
GND: C89.1 C90.1 C91.2 C102.1 C103.1 C104.1 C105.1 C106.1 C107.2 C108.2 C109.1 C110.1 C111.1 C112.1 C113.1 C114.1 C115.1 C116.1 C117.1 C118.1 C119.1 C120.1 R32.2 R36.1 R37.1 R39.2 R42.2 U10.19(GND) U10.29(EP) U11.77(EP) U12.3(GND) U12.8(GND) U13.3(GND) U13.8(GND) U14.4(GND) Y3.2(GND) Y3.4(GND)
VBUS: C89.2 C90.2 R28.1 R29.1 R34.2 U10.26(VCC5V) U10.27(Vconn_5V_in)
VCC1.05V-VL822: C109.2 C110.2 C111.2 C112.2 C113.2 C114.2 C115.2 C116.2 C117.2 C118.2 C119.2 C120.2 U11.5(VCCI0I) U11.8(VCC10I) U11.11(VDD) U11.14(VCC10I) U11.27(VCC10I) U11.30(VDD) U11.33(VCC10I) U11.36(VCC10I) U11.48(VDD) U11.51(VCC10I) U11.54(VCC10I) U11.67(VDD)
VCC3.3V-VL822: C102.2 C103.2 C104.2 C105.2 C106.2 R30.2 R31.2 R33.2 R35.2 R38.2 R40.2 R43.2 R44.2 R45.2 R46.2 R47.1 U11.17(VCC33I) U11.24(VCC33I) U11.46(VCC33I) U11.62(VCC33I) U11.73(VCC33I) U14.8(VCC)
cap_SSTX1_N: C93.2 U11.4(SSTX1N)
cap_SSTX1_P: C92.2 U11.3(SSTX1P)
cap_SSTX2_N: C97.2 U11.13(SSTX2N)
cap_SSTX2_P: C96.2 U11.12(SSTX2P)
cap_SSTX3_N: C100.2 U11.26(SSTX3N)
cap_SSTX3_P: C98.2 U11.25(SSTX3P)
cap_SSTX4_N: C99.2 U11.32(SSTX4N)
cap_SSTX4_P: C101.2 U11.31(SSTX4P)
cap_SSTX_N: C95.2 U11.49(SSTX0N)
cap_SSTX_P: C94.2 U11.50(SSTX0P)
HSD1_N: U11.10(HSD1N)
HSD1_P: U11.9(HSD1P)
HSD2_N: U11.19(HSD2N)
HSD2_P: U11.18(HSD2P)
HSD3_N: U11.23(HSD3N)
HSD3_P: U11.22(HSD3P)
HSD4_N: U11.38(HSD4-)
HSD4_P: U11.37(HSD4P)
IN_CC1: U10.1(CC1)
IN_CC2: U10.28(CC2)
IN_SSRX1_N: U10.7(RX1_N) U12.2(IO2) U12.9(NC)
IN_SSRX1_P: U10.6(RX1_P) U12.1(IO1) U12.10(NC)
IN_SSRX2_N: U10.9(RX2_P) U12.5(IO4) U12.6(NC)
IN_SSRX2_P: U10.8(RX2_N) U12.4(IO3) U12.7(NC)
IN_SSTX1_N: U10.3(TX1_N) U13.2(IO2) U13.9(NC)
IN_SSTX1_P: U10.2(TX1_P) U13.1(IO1) U13.10(NC)
IN_SSTX2_N: U10.4(TX2_N) U13.4(IO3) U13.7(NC)
IN_SSTX2_P: U10.5(TX2_P) U13.5(IO4) U13.6(NC)
SPICLK: U11.70(USBLED2/SPICK) U14.6(SLCK)
SPICS: U11.72(USBLED4/SPICS) U14.1(CS#)
SPISI: U11.69(USBLED1/SPISI) U14.5(SI)
SPISO: U11.71(USBLED3/SPISO) U14.2(SO)
SSRX1_N: U11.7(SSRX1N)
SSRX1_P: U11.6(SSRX1P)
SSRX2_N: U11.16(SSRX2N)
SSRX2_P: U11.15(SSRX2P)
SSRX3_N: U11.29(SSRX3N)
SSRX3_P: U11.28(SSRX3P)
SSRX4_N: U11.35(SSRX4N)
SSRX4_P: U11.34(SSRX4P)
SSRX_N: U10.17(RX_N) U11.53(SSRX0P)
SSRX_P: U10.18(RX_P) U11.52(SSRX0N)
SSTX1_N: C93.1
SSTX1_P: C92.1
SSTX2_N: C97.1
SSTX2_P: C96.1
SSTX3_N: C100.1
SSTX3_P: C98.1
SSTX4_N: C99.1
SSTX4_P: C101.1
SSTX_N: C95.1 U10.21(TXP)
SSTX_P: C94.1 U10.20(TXN)
USBD_N: U11.56(HSD0N)
USBD_P: U11.55(HSD0P)
XIN: C108.1 U11.45(USB3XI) Y3.3(XTAL_P)
XOUT: C107.1 U11.44(USB3XO) Y3.1(XTAL_N)
NetC91_1: C91.1 R30.1 U11.68(RESET#)
NetR28_2: R28.2 U10.24(Current_Setting_in2)
NetR29_2: R29.2 U10.23(Current_Setting_in1)
NetR31_1: R31.1 U11.66(GPIO8/SMCLK)
NetR32_1: R32.1 U11.74(TESTEN)
NetR33_1: R33.1 U11.65(GPIO7/SMDAT)
NetR34_1: R34.1 U10.25(CE)
NetR35_1: R35.1 U11.75(USBOC2)
NetR36_2: R36.2 U10.13(High_Z_CC)
NetR37_2: R37.2 U10.10(REXT)
NetR38_1: R38.1 U11.1(USBOC1)
NetR39_1: R39.1 U11.47(REXT)
NetR40_1: R40.1 R41.2 R42.1
NetR41_1: R41.1 U11.43(VBUSDET0)
NetR43_1: R43.1 U11.41(USBOC0)
NetR44_1: R44.1 U11.40(USBOC4)
NetR45_1: R45.1 U11.20(USBOC3)
NetR46_1: R46.1 U14.3(WP#)
NetR47_2: R47.2 U14.7(HOLD#)

Not connected (* = marked no-connect by the designer): U10 11(Vconn_OC)* 12(Vconn_UVLO)* 14(Current_Setting_out1)* 15(Current_Setting_out2)* 16(Attacned_Status)* 22(ORI_STATUS)*; U11 2(USBPE1)* 21(USBPE3)* 39(USBPE4)* 42(USBPE0)* 57(GPIO0/HID0)* 58(GPIO1/HID1)* 59(GPIO2/HID2)* 60(GPIO3/HID3)* 61(GPIO4/HID4)* 63(GPIO5/WAKE)* 64(GPIO6/USBSUS)* 76(USBPE2)*

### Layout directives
differential pair: cap_SSTX1_N, cap_SSTX1_P, cap_SSTX2_N, cap_SSTX2_P, cap_SSTX3_N, cap_SSTX3_P, cap_SSTX4_N, cap_SSTX4_P, cap_SSTX_N, cap_SSTX_P, HSD1_N, HSD1_P, HSD2_N, HSD2_P, HSD3_N, HSD3_P, HSD4_N, HSD4_P, IN_SSRX1_N, IN_SSRX1_P, IN_SSRX2_N, IN_SSRX2_P, IN_SSTX1_N, IN_SSTX1_P, IN_SSTX2_N, IN_SSTX2_P, SSRX1_N, SSRX1_P, SSRX2_N, SSRX2_P, SSRX3_N, SSRX3_P, SSRX4_N, SSRX4_P, SSRX_N, SSRX_P, SSTX1_N, SSTX1_P, SSTX2_N, SSTX2_P, SSTX3_N, SSTX3_P, SSTX4_N, SSTX4_P, SSTX_N, SSTX_P, USBD_N, USBD_P
net class USB; rule Differential Pairs Routing [Pref Gap = 5mil    Min Gap  = 5mil    Max Gap  = 5milPref Width = 5.1mil    Min Width  = 5.1mil    Max Width  = 5.1mil]; rule Routing Via Style [Pref Size = 0.4mm    Pref Hole Size = 0.3mm]: cap_IN_SSRX1_N, cap_IN_SSRX1_P, cap_IN_SSRX2_N, cap_IN_SSRX2_P, cap_IN_SSTX1_N, cap_IN_SSTX1_P, cap_IN_SSTX2_N, cap_IN_SSTX2_P, cap_SSRX1_N, cap_SSRX1_P, cap_SSRX2_N, cap_SSRX2_P, cap_SSRX3_N, cap_SSRX3_P, cap_SSRX4_N, cap_SSRX4_P, cap_SSTX1_N, cap_SSTX1_P, cap_SSTX2_N, cap_SSTX2_P, cap_SSTX3_N, cap_SSTX3_P, cap_SSTX4_N, cap_SSTX4_P, cap_SSTX_N, cap_SSTX_P, HSD1_N, HSD1_P, HSD2_N, HSD2_P, HSD3_N, HSD3_P, HSD4_N, HSD4_P, IN_CC1, IN_CC2, IN_SSRX1_N, IN_SSRX1_P, IN_SSRX2_N, IN_SSRX2_P, IN_SSTX1_N, IN_SSTX1_P, IN_SSTX2_N, IN_SSTX2_P, SSRX1_N, SSRX1_P, SSRX2_N, SSRX2_P, SSRX3_N, SSRX3_P, SSRX4_N, SSRX4_P, SSRX_N, SSRX_P, SSTX1_N, SSTX1_P, SSTX2_N, SSTX2_P, SSTX3_N, SSTX3_P, SSTX4_N, SSTX4_P, SSTX_N, SSTX_P, USBD_N, USBD_P

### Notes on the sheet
- Labels drawn without touching a wire or pin: cap_IN_SSRX1_N, cap_IN_SSRX1_P, cap_IN_SSRX2_N, cap_IN_SSRX2_P, cap_IN_SSTX1_N, cap_IN_SSTX1_P, cap_IN_SSTX2_N, cap_IN_SSTX2_P, cap_SSRX1_N, cap_SSRX1_P, cap_SSRX2_N, cap_SSRX2_P, cap_SSRX3_N, cap_SSRX3_P, cap_SSRX4_N, cap_SSRX4_P, cap_SSTX1_N, cap_SSTX1_P, cap_SSTX2_N, cap_SSTX2_P, cap_SSTX3_N, cap_SSTX3_P, cap_SSTX4_N, cap_SSTX4_P, cap_SSTX_N, cap_SSTX_P, HSD1_N, HSD1_P, HSD2_N, HSD2_P, HSD3_N, HSD3_P, HSD4_N, HSD4_P, IN_CC1, IN_CC2, IN_SSRX1_N, IN_SSRX1_P, IN_SSRX2_N, IN_SSRX2_P, IN_SSTX1_N, IN_SSTX1_P, IN_SSTX2_N, IN_SSTX2_P, SSRX1_N, SSRX1_P, SSRX2_N, SSRX2_P, SSRX3_N, SSRX3_P, SSRX4_N, SSRX4_P, SSRX_N, SSRX_P, SSTX1_N, SSTX1_P, SSTX2_N, SSTX2_P, SSTX3_N, SSTX3_P, SSTX4_N, SSTX4_P, SSTX_N, SSTX_P, USBD_N, USBD_P

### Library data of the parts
C89-C120 = C: 无极性贴片电容; 版权归属: 源创客; 材质: X7R
R28-R47 = R: 贴片电阻; 版权归属: 源创客
U12 U13 = TPD4E02B04: ESD
U14 = P25D40H
Y3 = Crystal

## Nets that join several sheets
GND: pwr (49 pins), connector (32 pins), jmb575 (60 pins), vl822 (37 pins)
VBUS: pwr (12 pins), connector (6 pins), jmb575 (8 pins), vl822 (7 pins)
VCC1.05V-VL822: pwr (8 pins), vl822 (24 pins)
VCC3.3V-VL822: pwr (6 pins), vl822 (22 pins)
VCC5V-A: pwr (10 pins), connector (J1.P7 J1.P8 J1.P9)
VCC5V-B: pwr (10 pins), connector (J2.P7 J2.P8 J2.P9)
VCC12V: pwr (16 pins), connector (6 pins)
VIN: pwr (5 pins), connector (CON1.1)
GPIO4-B: connector (LED2.2), jmb575 (U6.8)
GPIO4-C: connector (LED4.2), jmb575 (U8.8)
HSD1_N: jmb575 (U8.13), vl822 (U11.10)
HSD1_P: jmb575 (U8.15), vl822 (U11.9)
HSD2_N: connector (J5.2), vl822 (U11.19)
HSD2_P: connector (J5.3), vl822 (U11.18)
HSD3_N: connector (J4.2), vl822 (U11.23)
HSD3_P: connector (J4.3), vl822 (U11.22)
HSD4_N: jmb575 (U6.13), vl822 (U11.38)
HSD4_P: jmb575 (U6.15), vl822 (U11.37)
IN_CC1: connector (J3.A5), vl822 (U10.1)
IN_CC2: connector (J3.B5), vl822 (U10.28)
IN_SSRX1_N: connector (J3.B11), vl822 (U10.7 U12.2 U12.9)
IN_SSRX1_P: connector (J3.B10), vl822 (U10.6 U12.1 U12.10)
IN_SSRX2_N: connector (J3.A11), vl822 (U10.9 U12.5 U12.6)
IN_SSRX2_P: connector (J3.A10), vl822 (U10.8 U12.4 U12.7)
IN_SSTX1_N: connector (J3.A3), vl822 (U10.3 U13.2 U13.9)
IN_SSTX1_P: connector (J3.A2), vl822 (U10.2 U13.1 U13.10)
IN_SSTX2_N: connector (J3.B2), vl822 (U10.4 U13.4 U13.7)
IN_SSTX2_P: connector (J3.B3), vl822 (U10.5 U13.5 U13.6)
RX1_N: connector (C41.2), jmb575 (U8.31)
RX1_P: connector (C43.2), jmb575 (U8.30)
RX2_N: connector (C42.2), jmb575 (U6.31)
RX2_P: connector (C44.2), jmb575 (U6.30)
SSRX1_N: jmb575 (C86.1), vl822 (U11.7)
SSRX1_P: jmb575 (C85.1), vl822 (U11.6)
SSRX2_N: connector (J5.5), vl822 (U11.16)
SSRX2_P: connector (J5.6), vl822 (U11.15)
SSRX3_N: connector (J4.6), vl822 (U11.29)
SSRX3_P: connector (J4.5), vl822 (U11.28)
SSRX4_N: jmb575 (C64.1), vl822 (U11.35)
SSRX4_P: jmb575 (C63.1), vl822 (U11.34)
SSTX1_N: jmb575 (U8.22), vl822 (C93.1)
SSTX1_P: jmb575 (U8.23), vl822 (C92.1)
SSTX2_N: connector (J5.8), vl822 (C97.1)
SSTX2_P: connector (J5.9), vl822 (C96.1)
SSTX3_N: connector (J4.9), vl822 (C100.1)
SSTX3_P: connector (J4.8), vl822 (C98.1)
SSTX4_N: jmb575 (U6.22), vl822 (C99.1)
SSTX4_P: jmb575 (U6.23), vl822 (C101.1)
TX1_N: connector (C39.2), jmb575 (U8.33)
TX1_P: connector (C37.2), jmb575 (U8.34)
TX2_N: connector (C40.2), jmb575 (U6.33)
TX2_P: connector (C38.2), jmb575 (U6.34)
USBD_N: connector (J3.A7 J3.B7), vl822 (U11.56)
USBD_P: connector (J3.A6 J3.B6), vl822 (U11.55)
